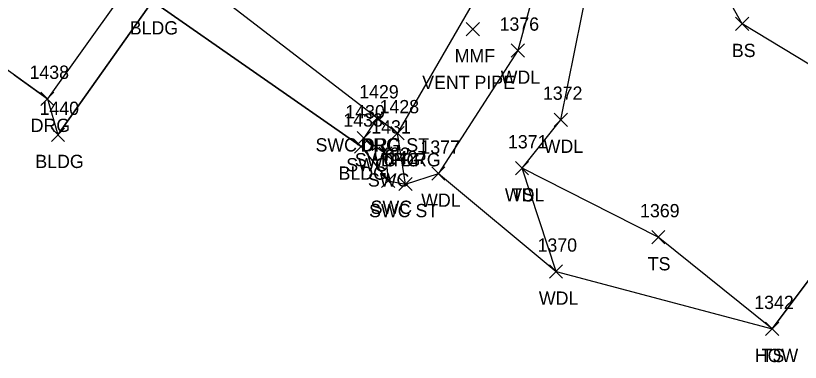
# Model space of a CAD drawing. Extents: x 1461855 to 1464118, y 556196 to 557441.
# Drawn here: x 1462417.3 to 1462535.4, y 556225 to 556277.2 of the extents above; entities that cross this region are included whole.
import ezdxf

# ---------------------------------------------------------------- set-up
doc = ezdxf.new("R2010")
doc.units = 0
for name, color, linetype in [('L_A', 7, 'Continuous'), ('L_C', 7, 'Continuous'), ('L_I', 7, 'Continuous'), ('L_TIC', 7, 'Continuous'), ('LAWA', 7, 'Continuous'), ('LBC', 7, 'Continuous'), ('LELB', 7, 'Continuous'), ('LSOGP', 7, 'Continuous'), ('R_A', 7, 'Continuous'), ('R_I', 7, 'Continuous'), ('R_TIC', 7, 'Continuous'), ('RDG', 7, 'Continuous'), ('RSW', 7, 'Continuous')]:
    doc.layers.add(name, color=color, linetype=linetype)

msp = doc.modelspace()

# ---------------------------------------------------------------- linework, layer by layer
at = {"layer": 'L_TIC'}
for points in [[(1462525.69, 556274.99), (1462527.69, 556276.99)], [(1462527.69, 556274.99), (1462525.69, 556276.99)], [(1462485.1, 556274.18), (1462487.1, 556276.18)], [(1462487.1, 556274.18), (1462485.1, 556276.18)], [(1462491.89, 556270.96), (1462493.89, 556272.96)], [(1462493.89, 556270.96), (1462491.89, 556272.96)], [(1462498.36, 556260.55), (1462500.36, 556262.55)], [(1462500.36, 556260.55), (1462498.36, 556262.55)], [(1462422.63, 556258.27), (1462424.63, 556260.27)], [(1462424.63, 556258.27), (1462422.63, 556260.27)], [(1462468.3, 556256.51), (1462470.3, 556258.51)], [(1462470.3, 556256.51), (1462468.3, 556258.51)], [(1462492.52, 556253.23), (1462494.52, 556255.23)], [(1462494.52, 556253.23), (1462492.52, 556255.23)], [(1462492.52, 556253.23), (1462494.52, 556255.23)], [(1462494.52, 556253.23), (1462492.52, 556255.23)], [(1462479.92, 556252.43), (1462481.92, 556254.43)], [(1462481.92, 556252.43), (1462479.92, 556254.43)], [(1462513.05, 556242.85), (1462515.05, 556244.85)], [(1462515.05, 556242.85), (1462513.05, 556244.85)], [(1462497.64, 556237.67), (1462499.64, 556239.67)], [(1462499.64, 556237.67), (1462497.64, 556239.67)], [(1462530.2, 556229.03), (1462532.2, 556231.03)], [(1462532.2, 556229.03), (1462530.2, 556231.03)], [(1462530.2, 556229.03), (1462532.2, 556231.03)], [(1462532.2, 556229.03), (1462530.2, 556231.03)]]:
    msp.add_lwpolyline(points, dxfattribs=at)
at = {"layer": 'LAWA'}
msp.add_lwpolyline([(1462498.64, 556238.67), (1462493.52, 556254.23), (1462499.36, 556261.55), (1462503.56, 556282.49), (1462496.56, 556285.39), (1462492.89, 556271.96), (1462480.92, 556253.43)], dxfattribs=at)
at = {"layer": 'LBC'}
for points in [[(1462469.3, 556257.51), (1462437.85, 556279.39), (1462423.63, 556259.27)], [(1462579.15, 556229.86), (1462559.45, 556244.33), (1462548.24, 556252.72), (1462531.2, 556230.03)]]:
    msp.add_lwpolyline(points, dxfattribs=at)
at = {"layer": 'LELB'}
for points in [[(1462566.05, 556253.25), (1462551.07, 556261.22), (1462526.69, 556275.99), (1462519.12, 556289.53), (1462518.52, 556300.62), (1462520.17, 556306.41), (1462512.78, 556309.97), (1462497.67, 556320.06), (1462474.58, 556337.93), (1462471.37, 556338.06), (1462470.04, 556339.66), (1462464.04, 556350.54), (1462457.4, 556355.85)], [(1462531.2, 556230.03), (1462514.05, 556243.85), (1462493.52, 556254.23)]]:
    msp.add_lwpolyline(points, dxfattribs=at)
at = {"layer": 'LSOGP'}
msp.add_lwpolyline([(1462417.02, 556268.29), (1462422.03, 556264.7), (1462423.63, 556259.27), (1462437.85, 556279.39), (1462469.3, 556257.51), (1462473.36, 556252.36), (1462475.99, 556251.86), (1462480.92, 556253.43), (1462498.64, 556238.67), (1462531.2, 556230.03), (1462548.24, 556252.72)], dxfattribs=at)
at = {"layer": 'R_TIC'}
for points in [[(1462421.03, 556263.7), (1462423.03, 556265.7)], [(1462423.03, 556263.7), (1462421.03, 556265.7)], [(1462470.7, 556260.76), (1462472.7, 556262.76)], [(1462472.7, 556260.76), (1462470.7, 556262.76)], [(1462470.7, 556260.76), (1462472.7, 556262.76)], [(1462472.7, 556260.76), (1462470.7, 556262.76)], [(1462468.69, 556257.76), (1462470.69, 556259.76)], [(1462470.69, 556257.76), (1462468.69, 556259.76)], [(1462473.76, 556258.52), (1462475.76, 556260.52)], [(1462475.76, 556258.52), (1462473.76, 556260.52)], [(1462473.76, 556258.52), (1462475.76, 556260.52)], [(1462475.76, 556258.52), (1462473.76, 556260.52)], [(1462471.94, 556255.47), (1462473.94, 556257.47)], [(1462473.94, 556255.47), (1462471.94, 556257.47)], [(1462472.36, 556251.36), (1462474.36, 556253.36)], [(1462474.36, 556251.36), (1462472.36, 556253.36)], [(1462474.99, 556250.86), (1462476.99, 556252.86)], [(1462476.99, 556250.86), (1462474.99, 556252.86)]]:
    msp.add_lwpolyline(points, dxfattribs=at)
at = {"layer": 'RDG'}
for points in [[(1462447.88, 556349.7), (1462444.98, 556341.7), (1462446.33, 556330.64), (1462452.29, 556322.34), (1462451.77, 556321.22), (1462458.54, 556316.82), (1462486.7, 556297.43), (1462493.25, 556293.06), (1462488.21, 556282.83), (1462474.76, 556259.52)], [(1462471.7, 556261.76), (1462438.32, 556287.48), (1462422.03, 556264.7), (1462402, 556279.05), (1462397.58, 556285.55), (1462409, 556300.55), (1462420.82, 556315.87), (1462433.11, 556307.34), (1462433.65, 556308.39), (1462436.24, 556314.92), (1462427.47, 556321.19), (1462422.77, 556315.36)]]:
    msp.add_lwpolyline(points, dxfattribs=at)
at = {"layer": 'RSW'}
msp.add_lwpolyline([(1462475.99, 556251.86), (1462474.76, 556259.52), (1462471.7, 556261.76), (1462469.69, 556258.76), (1462472.94, 556256.47), (1462473.36, 556252.36)], dxfattribs=at)

# ---------------------------------------------------------------- texts
at = {"layer": 'L_A'}
for s, p in [('BLDG', (1462434.44, 556274.39)), ('BS', (1462525.13, 556270.99)), ('MMF', (1462483.38, 556270.18)), ('WDL', (1462490.31, 556266.96)), ('WDL', (1462496.78, 556256.55)), ('BLDG', (1462420.22, 556254.27)), ('BLDG', (1462465.89, 556252.51)), ('WDL', (1462478.33, 556248.43)), ('WDL', (1462490.94, 556249.23)), ('TS', (1462491.93, 556249.23)), ('TS', (1462512.46, 556238.85)), ('WDL', (1462496.06, 556233.67)), ('HOW', (1462528.58, 556225.03)), ('TS', (1462529.61, 556225.03))]:
    msp.add_text(s, height=2, dxfattribs=at).set_placement(p)
at = {"layer": 'L_C'}
msp.add_text('VENT PIPE', height=2, dxfattribs=at).set_placement((1462478.49, 556266.18))
at = {"layer": 'L_I'}
for s, p in [('1376', (1462490.14, 556274.96)), ('1372', (1462496.67, 556264.55)), ('1440', (1462420.85, 556262.27)), ('1433', (1462466.61, 556260.51)), ('1371', (1462491.4, 556257.23)), ('1371', (1462491.4, 556257.23)), ('1377', (1462478.22, 556256.43)), ('1369', (1462511.3, 556246.85)), ('1370', (1462495.86, 556241.67)), ('1342', (1462528.5, 556233.03)), ('1342', (1462528.5, 556233.03))]:
    msp.add_text(s, height=2, dxfattribs=at).set_placement(p)
at = {"layer": 'R_A'}
for s, p in [('DRG', (1462419.52, 556259.7)), ('SWC DRG ST', (1462462.42, 556256.76)), ('DRG', (1462469.19, 556256.76)), ('SWC DRG', (1462468.34, 556254.52)), ('DRG', (1462472.25, 556254.52)), ('SWC', (1462467.05, 556253.76)), ('SWC', (1462470.31, 556251.47)), ('SWC', (1462470.72, 556247.36)), ('SWC ST', (1462470.49, 556246.86))]:
    msp.add_text(s, height=2, dxfattribs=at).set_placement(p)
at = {"layer": 'R_I'}
for s, p in [('1438', (1462419.34, 556267.7)), ('1429', (1462469, 556264.76)), ('1429', (1462469, 556264.76)), ('1428', (1462472.07, 556262.52)), ('1428', (1462472.07, 556262.52)), ('1430', (1462466.91, 556261.76)), ('1431', (1462470.82, 556259.47)), ('1432', (1462470.67, 556255.36)), ('1427', (1462473.3, 556254.86))]:
    msp.add_text(s, height=2, dxfattribs=at).set_placement(p)

doc.saveas('drawing.dxf')
